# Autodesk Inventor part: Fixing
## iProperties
Created: 2006-11
Part Number: Fixing
Document SubType Name: Modeling
Designer: nfjf
Author: nfjf
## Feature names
1. Extrusion1
2. Extrusion2
3. Fillet1
4. Fillet2
5. Fillet3
6. Extrusion3
